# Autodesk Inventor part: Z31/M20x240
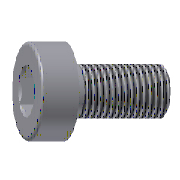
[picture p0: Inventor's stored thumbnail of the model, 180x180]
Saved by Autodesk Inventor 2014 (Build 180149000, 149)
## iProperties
Created: 2009-11
Part Number: Z31/M20x240
Material: Steel, Mild
Description: Hexagon Socket Head Cap Screw
Document SubType Name: Modeling
Designer: gaom
Standard Revision: 1
Manufacturer: HASCO
Language: en-US
Size Designation: M20x240
Categories: <MemberInstance><Categories><Category DisplayName="Mold" InternalName="349578f2-f4d4-4954-8c09-8e99297a61c0" Mnemonic="MOLD"><Category DisplayName="Fasteners" I
Mass: 0.133121 g
Surface Area: 2.01441 cm^2
Volume: 0.133121 cm^3
Density: 7.86 g/cm^3
Appearance: Steel
IsCustomPart: 0
Author: gaom
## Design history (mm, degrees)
body "Solid1"
revolve "Revolution1" stored, may be unused: angle "d44" = 90 deg
sketch "Sketch2"
  geometry: L1 (0, 9.815)-(8.5, 4.907); L2 (8.5, 4.907)-(8.5, -4.907); L3 (8.5, -4.907)-(0, -9.815); L4 (0, -9.815)-(-8.5, -4.907); L5 (-8.5, -4.907)-(-8.5, 4.907); L6 (-8.5, 4.907)-(0, 9.815); 3 further points
  constraints: 12 end point, 2 vertical alignment, 1 coincident, 14 other
extrude "Extrusion1" cut sketch "Sketch2" taper "d9" = 0 deg; stored distance "d45" = 10
thread "Thread1" dims "d10" = 52 (= b), "d11" = 0
chamfer "Chamfer1" distance "d12" = 1.25 (= 0.5 x P); stored, may be unused: second distance "d50" = 2, angle "d51" = 45 deg
fillet "Fillet1" dims "d13" = 1.25 (= 0.5 x P)
sketch "Sketch1"
  geometry: L1 (0, -292)-(0, 72) reference; L2 (9.815, 20)-(15, 20); L3 (15, 20)-(15, 0); L4 (15, 0)-(10, 0); L5 (10, 0)-(10, -240); L6 (10, -240)-(0, -240); L7 (0, 4.893)-(0, -240); L8 (0, 4.893)-(8.5, 10); L9 (8.5, 10)-(8.5, 18.685); L10 (8.5, 18.685)-(9.815, 20); 1 further point
  constraints: 18 end point, 4 vertical, 3 horizontal, 2 point on line
  dimensions: "d0" = 30 diameter of L3 L1 (= dk); "d1" = 20 distance between parallel lines of L4 L2 (= k); "d2" = 20 diameter of L5 L1 (= d); "d3" = 240 distance between parallel lines of L6 L4 (= L); "d4" = 59 deg angle of L1 L8; "d5" = 45 deg angle of L1 L10; "d6" = 17 diameter of L9 L1 (= sw); "d7" = 19.62991 diameter of L2.start L1 (= 1.1547 x sw); "d8" = 10 distance from line of L8.end L2 (= t)
other parameters: "d" = 20 [user parameter; used in 1 equation term], "L" = 240 [user parameter; used in 1 equation term], "dk" = 30 [user parameter; used in 1 equation term], "b" = 52 [user parameter; used in 1 equation term], "k" = 20 [user parameter; used in 1 equation term], "sw" = 17 [user parameter; used in 2 equation terms], "t" = 10 [user parameter; used in 1 equation term], "P" = 2.5 [user parameter; used in 2 equation terms], "d14" = 0, "d15" = 0, "d55" = 0
